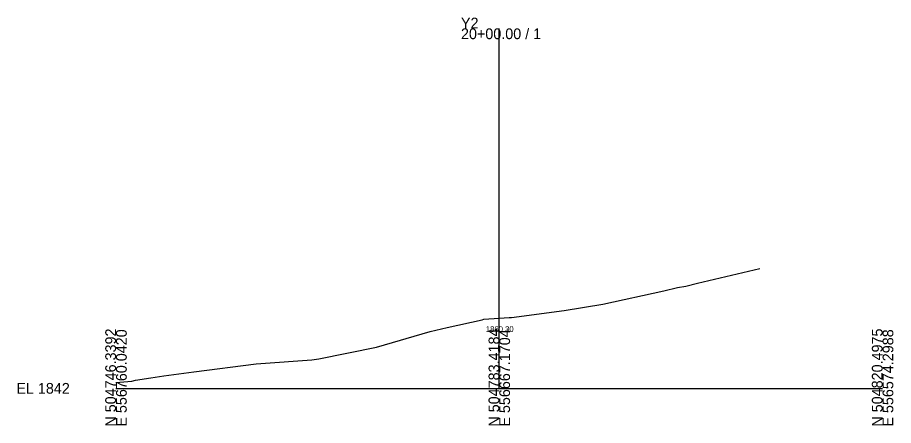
# Model space of a CAD drawing. Extents: x -26 to 1503, y -10 to 3574.
# Drawn here: x -25.7 to 202.8, y -9.7 to 96.8 of the extents above; entities that cross this region are included whole.
import ezdxf

# ---------------------------------------------------------------- set-up
doc = ezdxf.new("R2010")
doc.units = 0
for name, color, linetype in [('Default', 7, 'Continuous'), ('Exist Cross Section Cell', 7, 'Continuous'), ('Exist XS Center Line Elevation Label', 7, 'Continuous'), ('Exist XS Ground Line', 7, 'Continuous')]:
    doc.layers.add(name, color=color, linetype=linetype)

msp = doc.modelspace()

# ---------------------------------------------------------------- linework, layer by layer
at = {"layer": 'Exist Cross Section Cell'}
for p, q in [((100, 0), (100, 93.91)), ((0, 0), (100, 0)), ((100, 0), (200, 0))]:
    msp.add_line(p, q, dxfattribs=at)
at = {"layer": 'Exist XS Ground Line'}
for p, q in [((151.74, 27.46), (167.96, 31.3)), ((148.64, 26.64), (151.74, 27.46)), ((127.03, 21.98), (142.95, 25.42)), ((142.95, 25.42), (146.48, 26.31)), ((146.48, 26.31), (148.64, 26.64)), ((116.94, 20.34), (127.03, 21.98)), ((95.98, 18.02), (100, 18.3)), ((100, 18.3), (102.56, 18.48)), ((102.56, 18.48), (103.2, 18.51)), ((103.2, 18.51), (116.94, 20.34)), ((86.39, 15.87), (95.49, 17.9)), ((95.49, 17.9), (95.98, 18.02)), ((67.95, 10.77), (81.95, 14.85)), ((81.95, 14.85), (86.39, 15.87)), ((52.95, 7.73), (67.95, 10.77)), ((37.78, 6.51), (51.11, 7.44)), ((51.11, 7.44), (52.95, 7.73)), ((20.28, 4.28), (36.55, 6.43)), ((36.55, 6.43), (37.78, 6.51)), ((5.11, 2.11), (9.05, 2.71)), ((9.05, 2.71), (12.52, 3.29)), ((12.52, 3.29), (20.28, 4.28)), ((0, 1.49), (4.13, 1.83)), ((4.13, 1.83), (5.11, 2.11))]:
    msp.add_line(p, q, dxfattribs=at)

# ---------------------------------------------------------------- texts
at = {"layer": 'Default'}
msp.add_text('-', height=0.0001, dxfattribs=at).set_placement((0, 0))
at = {"layer": 'Exist Cross Section Cell'}
for s, p in [('Y2', (90, 93.91)), ('20+00.00 / 1', (90, 91.11)), ('EL 1842', (-26, -1.4))]:
    msp.add_text(s, height=2.8, dxfattribs=at).set_placement(p)
for s, p in [('N 504746.3392', (0, -10)), ('E 556760.0420', (2.8, -10)), ('N 504783.4184', (100, -10)), ('E 556667.1704', (102.8, -10)), ('N 504820.4975', (200, -10)), ('E 556574.2988', (202.8, -10))]:
    msp.add_text(s, height=2.8, rotation=90, dxfattribs=at).set_placement(p)
at = {"layer": 'Exist XS Center Line Elevation Label'}
msp.add_text('1860.30', height=1.5, dxfattribs=at).set_placement((96.49, 14.71))

doc.saveas('drawing.dxf')
